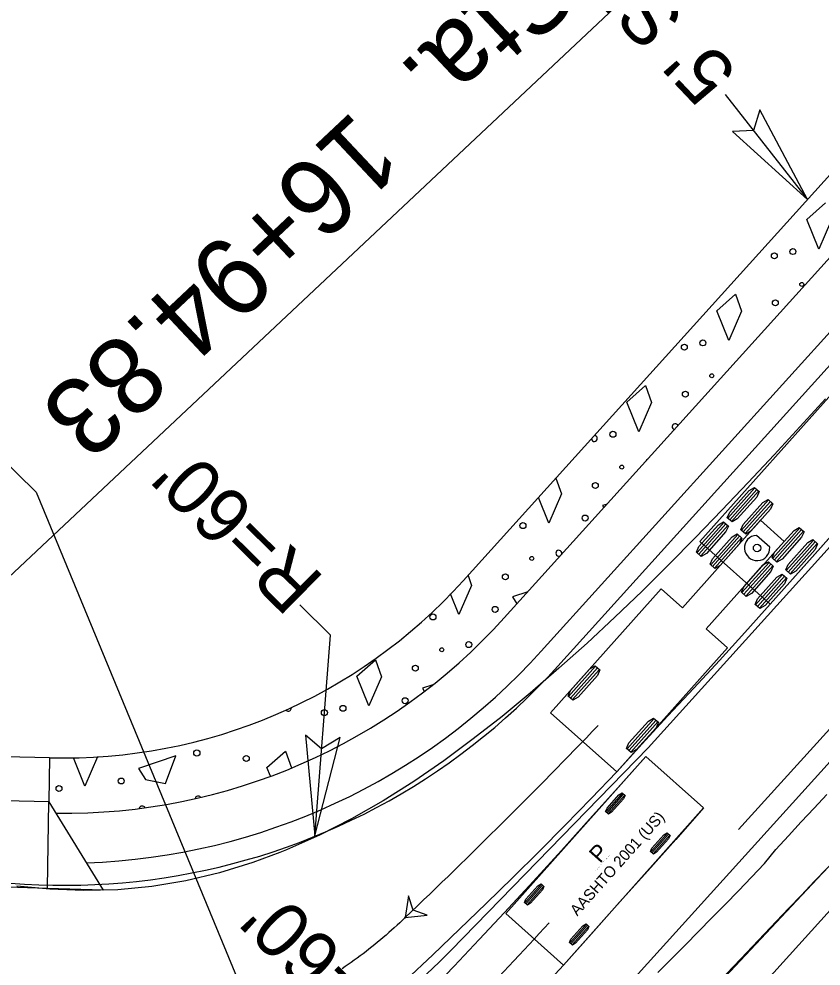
# Model space of a CAD drawing. Extents: x 1262642 to 1268358, y 767825 to 773481.
# Drawn here: x 1266795.4 to 1266867.8, y 772243.3 to 772328.8 of the extents above; entities that cross this region are included whole.
import ezdxf

# ---------------------------------------------------------------- set-up
doc = ezdxf.new("R2010")
doc.units = 0
for name, color, linetype in [('Old_Level_20', 7, 'Continuous'), ('Prop Conc 2ft 6in Curb and Gutter', 7, 'Continuous'), ('Prop Conc 4in Sidewalk', 7, 'Continuous'), ('Prop Dimension', 7, 'Continuous'), ('Prop Dimension Text', 7, 'Continuous'), ('Prop EOT', 7, 'Continuous'), ('Prop Horizontal Alignment', 7, 'Continuous'), ('Prop Horizontal Alignment Station Label', 7, 'Continuous'), ('Prop Lane Lines', 7, 'Continuous'), ('Prop Terminator CELL', 7, 'Continuous'), ('Scratch_Level_3', 7, 'Continuous')]:
    doc.layers.add(name, color=color, linetype=linetype)

msp = doc.modelspace()

# ---------------------------------------------------------------- linework, layer by layer
at = {"layer": 'Old_Level_20'}
for p, q in [((1266794.127, 772262.222), (1266798.126, 772262.116)), ((1266798.126, 772262.116), (1266798.065, 772258.117)), ((1266798.065, 772258.117), (1266794.066, 772258.223)), ((1266797.947, 772250.318), (1266798.065, 772258.117)), ((1266798.065, 772258.117), (1266802.964, 772250.149)), ((1266797.947, 772250.302), (1266788.957, 772250.576)), ((1266802.964, 772250.149), (1266797.947, 772250.302))]:
    msp.add_line(p, q, dxfattribs=at)
at = {"layer": 'Prop Conc 2ft 6in Curb and Gutter'}
for p, q in [((1267131.944, 772606.254), (1266835.453, 772278.077)), ((1267135.454, 772602.68), (1266839.163, 772274.725)), ((1267138.613, 772599.464), (1266842.502, 772271.708)), ((1266866.478, 772310.677), (1266868.164, 772312.174)), ((1266867.559, 772307.998), (1266866.478, 772310.677)), ((1266868.688, 772310.64), (1266867.559, 772307.998)), ((1266858.355, 772302.433), (1266860.041, 772303.93)), ((1266860.041, 772303.93), (1266860.565, 772302.396)), ((1266859.435, 772299.753), (1266858.355, 772302.433)), ((1266860.565, 772302.396), (1266859.435, 772299.753)), ((1266850.232, 772294.188), (1266851.918, 772295.686)), ((1266851.918, 772295.686), (1266852.442, 772294.152)), ((1266851.312, 772291.509), (1266850.232, 772294.188)), ((1266852.442, 772294.152), (1266851.312, 772291.509)), ((1266843.827, 772287.346), (1266844.318, 772285.907)), ((1266843.189, 772283.265), (1266842.248, 772285.598)), ((1266844.318, 772285.907), (1266843.189, 772283.265)), ((1266848.448, 772285.002), (1266848.02, 772284.857)), ((1266848.02, 772284.857), (1266848.145, 772284.666)), ((1266835.889, 772278.559), (1266836.195, 772277.663)), ((1266836.195, 772277.663), (1266835.066, 772275.02)), ((1266835.066, 772275.02), (1266834.312, 772276.889)), ((1266841.297, 772277.087), (1266839.896, 772276.613)), ((1266839.896, 772276.613), (1266840.305, 772275.988)), ((1266825.862, 772269.455), (1266827.548, 772270.953)), ((1266827.548, 772270.953), (1266828.072, 772269.418)), ((1266826.942, 772266.776), (1266825.862, 772269.455)), ((1266828.072, 772269.418), (1266826.942, 772266.776)), ((1266832.715, 772268.687), (1266831.773, 772268.369)), ((1266831.773, 772268.369), (1266831.947, 772268.103)), ((1266802.442, 772262.175), (1266801.312, 772259.533)), ((1266802.432, 772262.204), (1266802.442, 772262.175)), ((1266809.511, 772262.264), (1266806.143, 772261.126)), ((1266808.593, 772259.765), (1266809.511, 772262.264)), ((1266817.738, 772261.211), (1266819.425, 772262.708)), ((1266819.425, 772262.708), (1266819.945, 772261.184)), ((1266801.312, 772259.533), (1266800.274, 772262.108)), ((1266806.143, 772261.126), (1266806.787, 772260.14)), ((1266818.055, 772260.427), (1266817.738, 772261.211)), ((1266806.787, 772260.14), (1266808.593, 772259.765))]:
    msp.add_line(p, q, dxfattribs=at)
for centre, radius in [((1266863.541, 772307.398), 0.268), ((1266865.217, 772307.787), 0.268), ((1266866.02, 772304.82), 0.18), ((1266863.63, 772303.159), 0.268), ((1266857.094, 772299.543), 0.268), ((1266855.417, 772299.154), 0.268), ((1266857.896, 772296.576), 0.18), ((1266855.507, 772294.915), 0.268), ((1266848.971, 772291.298), 0.268), ((1266849.773, 772288.332), 0.18), ((1266847.384, 772286.671), 0.268), ((1266846.462, 772283.737), 0.268), ((1266840.847, 772283.054), 0.268), ((1266841.65, 772280.087), 0.18), ((1266839.26, 772278.426), 0.268), ((1266832.724, 772274.81), 0.268), ((1266838.339, 772275.493), 0.268), ((1266835.961, 772272.315), 0.268), ((1266833.526, 772271.843), 0.18), ((1266831.137, 772270.182), 0.268), ((1266830.216, 772267.249), 0.268), ((1266822.924, 772266.176), 0.268), ((1266824.601, 772266.565), 0.268), ((1266811.412, 772262.535), 0.285), ((1266815.876, 772262.04), 0.268), ((1266804.586, 772260.006), 0.268), ((1266798.971, 772259.322), 0.268)]:
    msp.add_circle(centre, radius, dxfattribs=at)
for centre, radius, start, end in [((1266854.586, 772291.982), 0.268, 20.20479, 255.60285), ((1266847.294, 772290.909), 0.268, 184.75105, 91.05659), ((1266852.208, 772288.804), 0.268, 111.99738, 163.81027), ((1266844.085, 772280.559), 0.268, 332.92264, 302.885), ((1266799.465, 772310.59), 48.5, 268.41722, 317.90382), ((1266799.465, 772310.59), 53.5, 269.17277, 317.90382), ((1266799.465, 772310.59), 58, 271.95347, 317.90382), ((1266819.654, 772266.599), 0.289, 219.5494, 346.5765), ((1266819.654, 772266.599), 0.289, 346.5765, 9.92674), ((1266811.531, 772258.355), 0.289, 39.38579, 166.24801), ((1266806.486, 772257.457), 0.292, 28.55158, 164.88831)]:
    msp.add_arc(centre, radius, start, end, dxfattribs=at)
at = {"layer": 'Prop Conc 4in Sidewalk'}
for p, q in [((1267131.944, 772606.254), (1266835.453, 772278.077)), ((1267135.454, 772602.68), (1266839.163, 772274.725))]:
    msp.add_line(p, q, dxfattribs=at)
for radius, start in [(48.5, 268.41722), (53.5, 269.17277)]:
    msp.add_arc((1266799.465, 772310.59), radius, start, 317.90382, dxfattribs=at)
at = {"layer": 'Prop Dimension'}
msp.add_line((1266822.06, 772255.007), (1266823.466, 772273.176), dxfattribs=at)
at = {"layer": 'Prop Dimension Text'}
for p, q in [((1266752.754, 772329.571), (1266796.901, 772286.072)), ((1266859.115, 772321.967), (1266866.527, 772312.472)), ((1266820.708, 772275.893), (1266823.466, 772273.176))]:
    msp.add_line(p, q, dxfattribs=at)
msp.add_lwpolyline([(1266796.901, 772286.072), (1266823.56, 772221.639)], dxfattribs=at)
at = {"layer": 'Prop EOT'}
msp.add_line((1267140.017, 772598.035), (1266843.986, 772270.367), dxfattribs=at)
msp.add_arc((1266799.465, 772310.59), 60, 239.37252, 317.90382, dxfattribs=at)
at = {"layer": 'Prop Horizontal Alignment'}
msp.add_line((1266770.936, 772153.71), (1267443.049, 772897.651), dxfattribs=at)
msp.add_arc((1275047.307, 780021.225), 11400, 222.9935866, 225.4043192, dxfattribs=at)
at = {"layer": 'Prop Horizontal Alignment Station Label'}
msp.add_line((1266683.114, 772173.743), (1266860.999, 772340.982), dxfattribs=at)
at = {"layer": 'Prop Lane Lines'}
for p, q in [((1267148.179, 772590.66), (1266852.149, 772262.993)), ((1267156.341, 772583.286), (1266860.311, 772255.619)), ((1266890.345, 772272.454), (1266862.92, 772242.098)), ((1266852.149, 772262.993), (1266834.367, 772244.75))]:
    msp.add_line(p, q, dxfattribs=at)
msp.add_arc((1266791.4, 772286.629), 60, 223.13275, 315.73419, dxfattribs=at)
at = {"layer": 'Prop Terminator CELL'}
for points in [[(1266859.767, 772318.612), (1266866.527, 772312.472), (1266862.22, 772320.59), (1266861.666, 772318.699)], [(1266821.213, 772264.136), (1266822.054, 772255.043), (1266824.357, 772263.94), (1266822.672, 772262.919)]]:
    msp.add_lwpolyline(points, close=True, dxfattribs=at)
at = {"layer": 'Scratch_Level_3'}
for p, q in [((1266841.285, 772223.318), (1266947.116, 772336.274)), ((1266888.785, 772317.431), (1266856.816, 772281.626)), ((1266863.156, 772275.965), (1266895.125, 772311.77)), ((1266859.338, 772283.731), (1266861.78, 772286.466)), ((1266859.509, 772283.578), (1266861.951, 772286.314)), ((1266859.68, 772283.426), (1266862.122, 772286.161)), ((1266860.569, 772282.632), (1266863.011, 772285.367)), ((1266860.74, 772282.48), (1266863.182, 772285.215)), ((1266860.91, 772282.327), (1266863.353, 772285.062)), ((1266862.302, 772283.542), (1266855.254, 772275.647)), ((1266864.441, 772281.633), (1266862.302, 772283.542)), ((1266856.563, 772280.623), (1266859.005, 772283.358)), ((1266856.734, 772280.47), (1266859.176, 772283.205)), ((1266856.905, 772280.318), (1266859.347, 772283.053)), ((1266863.391, 772280.112), (1266865.833, 772282.847)), ((1266863.562, 772279.96), (1266866.004, 772282.695)), ((1266857.793, 772279.524), (1266860.236, 772282.259)), ((1266857.964, 772279.371), (1266860.406, 772282.107)), ((1266858.135, 772279.219), (1266860.577, 772281.954)), ((1266863.125, 772281.098), (1266861.919, 772282.174)), ((1266863.733, 772279.807), (1266866.175, 772282.542)), ((1266856.816, 772281.626), (1266863.156, 772275.965)), ((1266857.392, 772273.738), (1266864.441, 772281.633)), ((1266864.621, 772279.013), (1266867.064, 772281.749)), ((1266864.792, 772278.861), (1266867.234, 772281.596)), ((1266864.963, 772278.708), (1266867.405, 772281.443)), ((1266860.616, 772277.004), (1266863.058, 772279.739)), ((1266860.787, 772276.852), (1266863.229, 772279.587)), ((1266860.957, 772276.699), (1266863.4, 772279.434)), ((1266861.846, 772275.905), (1266864.288, 772278.64)), ((1266862.017, 772275.753), (1266864.459, 772278.488)), ((1266862.188, 772275.6), (1266864.63, 772278.335)), ((1266853.339, 772277.357), (1266843.349, 772266.168)), ((1266855.254, 772275.647), (1266853.339, 772277.357)), ((1266863.156, 772275.965), (1266863.156, 772275.965)), ((1266859.307, 772272.029), (1266857.392, 772273.738)), ((1266849.316, 772260.84), (1266859.307, 772272.029)), ((1266887.239, 772271.972), (1266854.098, 772237.25)), ((1266844.963, 772267.631), (1266847.405, 772270.366)), ((1266845.134, 772267.479), (1266847.576, 772270.214)), ((1266845.305, 772267.326), (1266847.747, 772270.061)), ((1266843.349, 772266.168), (1266849.316, 772260.84)), ((1266850.247, 772262.914), (1266852.689, 772265.649)), ((1266850.418, 772262.761), (1266852.86, 772265.496)), ((1266850.588, 772262.608), (1266853.031, 772265.344)), ((1266851.927, 772262.23), (1266839.29, 772248.041)), ((1266857.154, 772257.575), (1266851.927, 772262.23)), ((1266849.316, 772260.84), (1266849.316, 772260.84)), ((1266848.332, 772257.23), (1266849.828, 772258.91)), ((1266848.437, 772257.136), (1266849.933, 772258.817)), ((1266848.542, 772257.043), (1266850.038, 772258.723)), ((1266844.518, 772243.386), (1266857.154, 772257.575)), ((1266852.392, 772253.614), (1266853.889, 772255.294)), ((1266852.497, 772253.52), (1266853.994, 772255.2)), ((1266852.602, 772253.427), (1266854.099, 772255.107)), ((1266841.016, 772249.015), (1266842.512, 772250.696)), ((1266841.121, 772248.922), (1266842.617, 772250.602)), ((1266841.226, 772248.828), (1266842.722, 772250.508)), ((1266839.29, 772248.041), (1266844.518, 772243.386)), ((1266845.076, 772245.399), (1266846.573, 772247.079)), ((1266845.181, 772245.305), (1266846.678, 772246.986)), ((1266845.286, 772245.212), (1266846.783, 772246.892)), ((1266844.518, 772243.386), (1266844.518, 772243.386))]:
    msp.add_line(p, q, dxfattribs=at)
for points in [[(1266868.154, 772294.484), (1266865.837, 772291.958), (1266863.51, 772289.44), (1266861.17, 772286.934), (1266858.811, 772284.446), (1266856.43, 772281.979), (1266856.43, 772281.979), (1266854.03, 772279.547), (1266851.599, 772277.146), (1266849.135, 772274.78), (1266846.634, 772272.455), (1266844.093, 772270.173), (1266841.509, 772267.941), (1266841.509, 772267.941), (1266838.958, 772265.832), (1266836.369, 772263.795), (1266833.721, 772261.837), (1266831.008, 772259.971), (1266828.229, 772258.215), (1266825.383, 772256.587), (1266822.472, 772255.105), (1266819.494, 772253.784), (1266818.89, 772253.54)], [(1266870.007, 772283.637), (1266867.723, 772281.08), (1266865.44, 772278.522), (1266863.156, 772275.965), (1266860.875, 772273.421), (1266858.579, 772270.891), (1266856.267, 772268.375), (1266853.934, 772265.878), (1266851.623, 772263.36), (1266849.316, 772260.84), (1266849.316, 772260.84), (1266847.016, 772258.411), (1266844.666, 772256.026), (1266842.302, 772253.655), (1266839.924, 772251.298), (1266837.532, 772248.956), (1266835.126, 772246.628), (1266832.706, 772244.314), (1266830.272, 772242.015)], [(1266851.927, 772262.23), (1266849.399, 772259.392), (1266846.869, 772256.557), (1266844.324, 772253.736), (1266841.761, 772250.93), (1266839.181, 772248.14), (1266839.181, 772248.14), (1266839.181, 772248.14), (1266836.91, 772245.712), (1266834.627, 772243.297), (1266832.329, 772240.896), (1266829.992, 772238.533), (1266829.754, 772238.301)], [(1266853.037, 772242.711), (1266854.262, 772243.947), (1266855.481, 772245.18), (1266856.694, 772246.411), (1266857.901, 772247.64), (1266859.103, 772248.867), (1266860.3, 772250.093), (1266861.492, 772251.318), (1266862.656, 772252.549), (1266863.674, 772253.831), (1266864.824, 772255.068), (1266865.974, 772256.304), (1266867.125, 772257.538), (1266868.277, 772258.771)], [(1266857.154, 772257.575), (1266854.638, 772254.726), (1266852.109, 772251.89), (1266849.572, 772249.061), (1266847.045, 772246.223), (1266844.518, 772243.386), (1266844.518, 772243.386), (1266842.236, 772240.925), (1266839.928, 772238.482), (1266837.606, 772236.051), (1266835.271, 772233.632), (1266835.036, 772233.391)], [(1266818.89, 772253.54), (1266816.467, 772252.645), (1266813.448, 772251.717), (1266810.418, 772250.997), (1266807.349, 772250.487), (1266804.267, 772250.195), (1266801.194, 772250.113), (1266798.144, 772250.227), (1266795.159, 772250.511)], [(1266859.448, 772242.855), (1266860.502, 772243.958), (1266861.57, 772245.078), (1266862.652, 772246.212), (1266863.748, 772247.359), (1266864.86, 772248.525), (1266865.994, 772249.713), (1266867.148, 772250.922), (1266868.31, 772252.139)], [(1266830.211, 772247.671), (1266829.97, 772247.442), (1266829.727, 772247.213), (1266829.482, 772246.987), (1266829.236, 772246.762), (1266828.988, 772246.539), (1266828.739, 772246.318), (1266828.488, 772246.099), (1266828.235, 772245.882), (1266827.98, 772245.666), (1266827.724, 772245.453), (1266827.467, 772245.242), (1266827.207, 772245.032), (1266826.946, 772244.825), (1266826.683, 772244.62), (1266826.419, 772244.417), (1266826.152, 772244.217), (1266825.885, 772244.018), (1266825.615, 772243.822), (1266825.344, 772243.629), (1266825.071, 772243.437), (1266824.796, 772243.249), (1266824.52, 772243.062)]]:
    msp.add_lwpolyline(points, dxfattribs=at)
for points in [[(1266859.722, 772283.388), (1266859.295, 772283.769), (1266859.509, 772284.267), (1266861.267, 772286.236), (1266861.737, 772286.504), (1266862.164, 772286.123), (1266861.951, 772285.625), (1266860.192, 772283.656)], [(1266860.953, 772282.289), (1266860.526, 772282.67), (1266860.74, 772283.168), (1266862.498, 772285.137), (1266862.968, 772285.405), (1266863.395, 772285.024), (1266863.182, 772284.526), (1266861.423, 772282.557)], [(1266856.947, 772280.28), (1266856.52, 772280.661), (1266856.734, 772281.159), (1266858.492, 772283.128), (1266858.962, 772283.396), (1266859.389, 772283.015), (1266859.176, 772282.517), (1266857.417, 772280.548)], [(1266863.775, 772279.769), (1266863.348, 772280.15), (1266863.562, 772280.648), (1266865.32, 772282.617), (1266865.79, 772282.885), (1266866.217, 772282.504), (1266866.004, 772282.007), (1266864.245, 772280.037)], [(1266858.178, 772279.181), (1266857.751, 772279.562), (1266857.964, 772280.06), (1266859.723, 772282.029), (1266860.193, 772282.297), (1266860.62, 772281.916), (1266860.406, 772281.418), (1266858.648, 772279.449)], [(1266865.006, 772278.67), (1266864.579, 772279.051), (1266864.792, 772279.549), (1266866.551, 772281.518), (1266867.021, 772281.786), (1266867.448, 772281.405), (1266867.234, 772280.908), (1266865.476, 772278.938)], [(1266861, 772276.661), (1266860.573, 772277.042), (1266860.787, 772277.54), (1266862.545, 772279.509), (1266863.015, 772279.777), (1266863.442, 772279.396), (1266863.229, 772278.899), (1266861.47, 772276.929)], [(1266862.231, 772275.562), (1266861.804, 772275.943), (1266862.017, 772276.441), (1266863.776, 772278.41), (1266864.246, 772278.678), (1266864.673, 772278.297), (1266864.459, 772277.8), (1266862.701, 772275.83)], [(1266845.347, 772267.288), (1266844.92, 772267.669), (1266845.134, 772268.167), (1266846.892, 772270.136), (1266847.363, 772270.404), (1266847.789, 772270.023), (1266847.576, 772269.526), (1266845.818, 772267.556)], [(1266850.631, 772262.571), (1266850.204, 772262.952), (1266850.418, 772263.449), (1266852.176, 772265.418), (1266852.646, 772265.687), (1266853.073, 772265.306), (1266852.86, 772264.808), (1266851.101, 772262.839)], [(1266848.568, 772257.02), (1266848.305, 772257.253), (1266848.436, 772257.559), (1266849.513, 772258.768), (1266849.802, 772258.933), (1266850.064, 772258.7), (1266849.933, 772258.394), (1266848.856, 772257.185)], [(1266852.628, 772253.403), (1266852.366, 772253.637), (1266852.497, 772253.942), (1266853.574, 772255.152), (1266853.863, 772255.317), (1266854.125, 772255.084), (1266853.994, 772254.778), (1266852.917, 772253.568)], [(1266841.252, 772248.805), (1266840.99, 772249.038), (1266841.12, 772249.344), (1266842.198, 772250.554), (1266842.486, 772250.719), (1266842.748, 772250.485), (1266842.618, 772250.18), (1266841.54, 772248.97)], [(1266830.211, 772247.671), (1266832.2, 772247.884), (1266830.936, 772248.361), (1266830.521, 772249.647)], [(1266845.313, 772245.189), (1266845.05, 772245.422), (1266845.181, 772245.728), (1266846.258, 772246.938), (1266846.547, 772247.102), (1266846.809, 772246.869), (1266846.678, 772246.563), (1266845.601, 772245.354)]]:
    msp.add_lwpolyline(points, close=True, dxfattribs=at)
for centre, radius in [((1266861.984, 772281.033), 0.34), ((1266830.211, 772247.671), 0.0417), ((1266830.211, 772247.671), 0.0417)]:
    msp.add_circle(centre, radius, dxfattribs=at)
for centre, radius, start, end in [((1266861.984, 772281.033), 1.143, 93.23946, 3.23946), ((1266447.801, 772649.354), 554.605, 313.59199, 316.13258), ((1266387.332, 772668.474), 620.729, 315.286422, 317.261141)]:
    msp.add_arc(centre, radius, start, end, dxfattribs=at)

# ---------------------------------------------------------------- texts
at = {"layer": 'Prop Dimension'}
msp.add_text("R=60'", height=5, rotation=135.42387, dxfattribs=at).set_placement((1266823.05, 772278.27))
at = {"layer": 'Prop Dimension Text'}
for s, rotation, p in [("5' SIDEWALK", 133.49554, (1266860.361, 772324.051)), ("R=60'", 135.42387, (1266831.041, 772238.278))]:
    msp.add_text(s, height=5, rotation=rotation, dxfattribs=at).set_placement(p)
at = {"layer": 'Prop Horizontal Alignment Station Label'}
msp.add_text('PC Sta.  16+94.83', height=7, rotation=223.23333, dxfattribs=at).set_placement((1266852.873, 772346.323))
at = {"layer": 'Scratch_Level_3'}
for s, height, p in [('AASHTO 2001 (US)', 1, (1266845.748, 772247.766)), ('P', 1.5, (1266847.8, 772252.514)), ('(c) 2016 Transoft Solutions, Inc. All rights reserved.', 0.06, (1266847.431, 772251.875))]:
    msp.add_text(s, height=height, rotation=48.31281, dxfattribs=at).set_placement(p)

doc.saveas('drawing.dxf')
